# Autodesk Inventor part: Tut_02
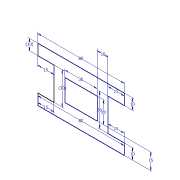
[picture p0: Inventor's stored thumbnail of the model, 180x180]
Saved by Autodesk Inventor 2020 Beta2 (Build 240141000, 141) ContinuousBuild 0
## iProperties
Created: 2019-02
Part Number: Tut_02
Material: Generic
Document SubType Name: Modeling
Designer: LENOVO-CADCIM
Density: 1 g/cm^3
Appearance: Default
Author: LENOVO-CADCIM
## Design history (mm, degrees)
sketch "Sketch1"
  geometry: L1 (0, 0)-(80, 0); L2 (80, 0)-(80, 10); L3 (80, 10)-(65, 10); L4 (65, 10)-(65, 40); L5 (65, 40)-(80, 40); L6 (80, 40)-(80, 50); L7 (80, 50)-(0, 50); L8 (0, 50)-(0, 40); L9 (0, 40)-(15, 40); L10 (15, 40)-(15, 10); L11 (15, 10)-(0, 10); L12 (0, 10)-(0, 0); L13 (25, 15)-(55, 15); L14 (55, 15)-(55, 35); L15 (55, 35)-(25, 35); L16 (25, 35)-(25, 15); 1 further point
  constraints: 32 end point, 6 perpendicular, 6 point on line, 2 horizontal, 2 parallel, 1 coincident, 1 collinear
  dimensions: "d0" = 80 distance of L1.start L1.end; "d1" = 10 distance of L1.end L2.end; "d2" = 15 distance of L2.end L3.end; "d3" = 30 distance of L3.end L4.end; "d4" = 15 distance of L4.end L5.end; "d5" = 10 distance of L5.end L6.end; "d6" = 80 distance of L6.end L7.end; "d7" = 10 distance of L7.end L8.end (derived); "d8" = 15 distance of L8.end L9.end; "d9" = 30 distance of L9.end L10.end (derived); "d10" = 15 distance of L10.end L11.end; "d11" = 30 distance of L15.end L14.end; "d12" = 20 distance of L14.end L13.end; "d14" = 15 distance between parallel lines of L13 L1; "d15" = 10 distance between parallel lines of L14 L4
